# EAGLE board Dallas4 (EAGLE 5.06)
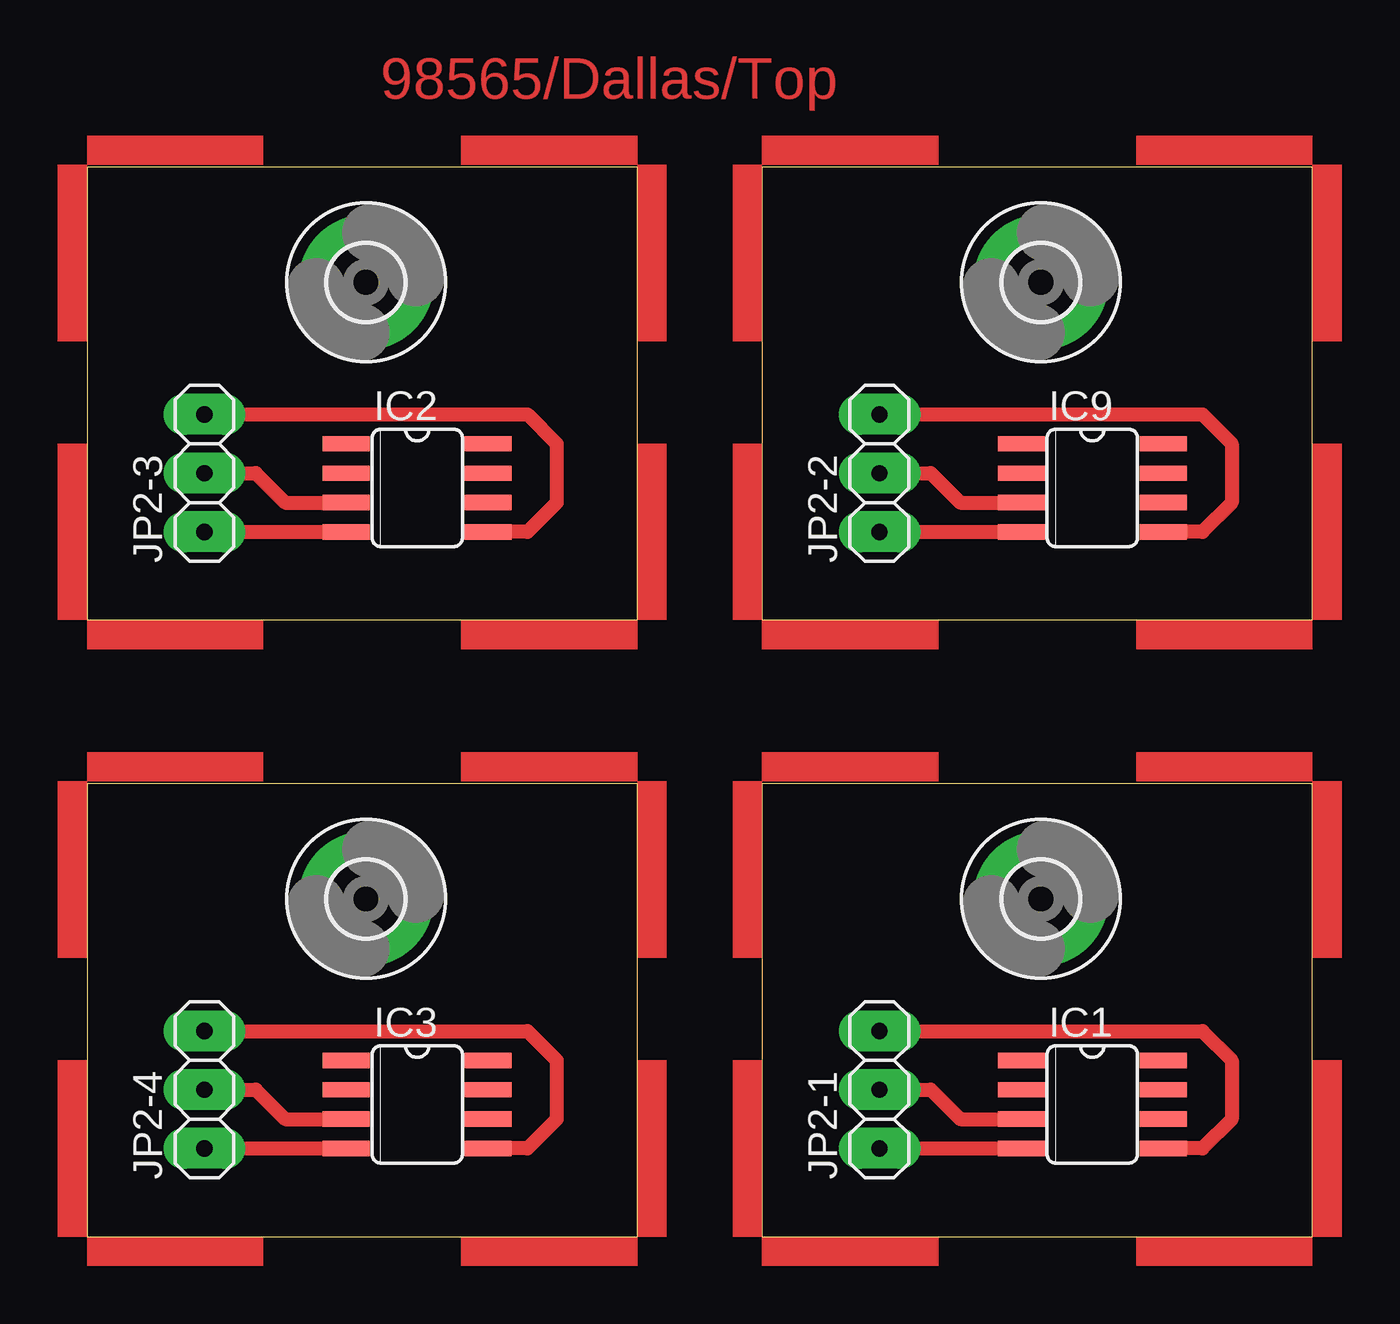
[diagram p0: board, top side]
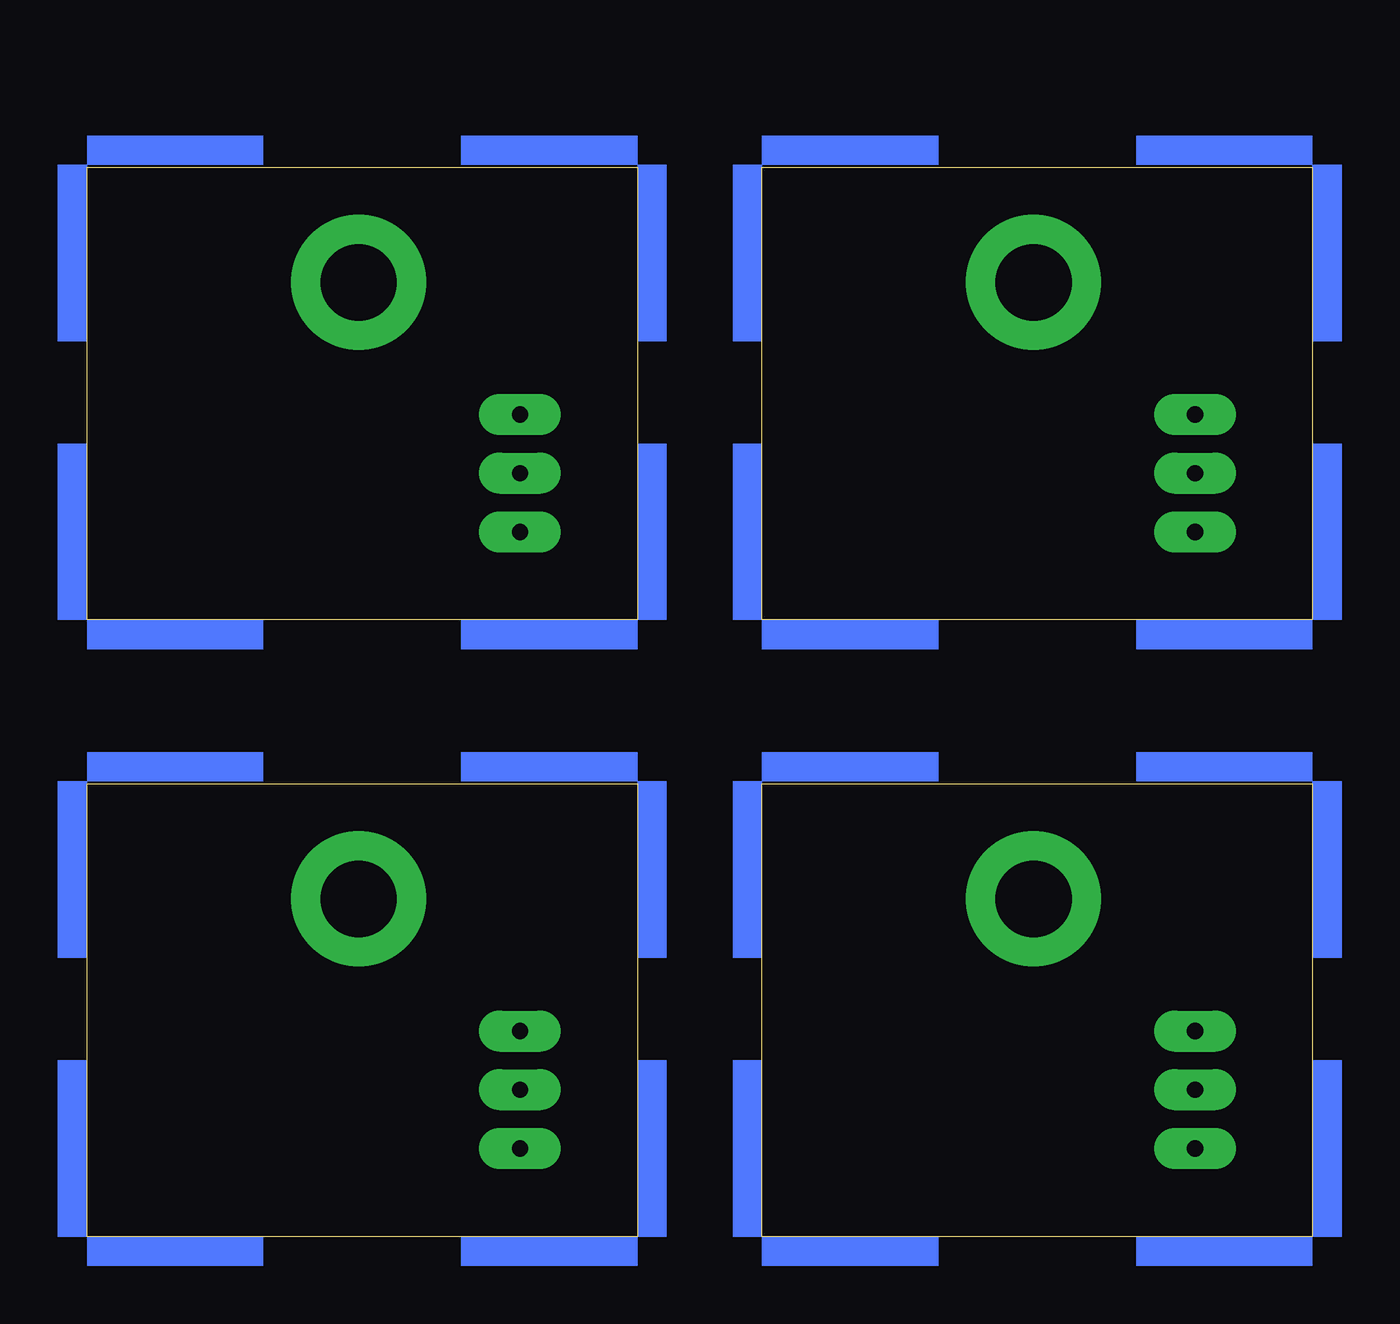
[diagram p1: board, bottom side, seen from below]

Size 53.02 x 46.26 mm. Coordinates in mm from the lower left corner, seen from the top.
Outline: 29.21,26.67 53.02,26.67 53.02,46.26 29.21,46.26 29.21,26.67
Outline: 29.21,0 53.02,0 53.02,19.59 29.21,19.59 29.21,0
Outline: 0,26.67 23.81,26.67 23.81,46.26 0,46.26 0,26.67
Outline: 0,0 23.81,0 23.81,19.59 0,19.59 0,0
Copper layers (1*16): Top 0.035mm / dielectric 1.5mm / Bottom 0.035mm
Design rules "default": minimum track width 10mil, minimum drill 24mil, track to track 8mil, track to pad 8mil, pad to pad 8mil, via to via 8mil, smd to smd 8mil, copper to edge 40mil, drill to drill 8mil, minimum pad ring 10mil, minimum via ring 8mil, stop-mask expansion 4mil, vias tented up to drill 0mil, thermal gap 10mil

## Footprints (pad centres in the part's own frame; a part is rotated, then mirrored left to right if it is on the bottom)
3,3-PAD = drill 3.3 pad 5.842 round: B3,3 0,0
SO08 = smd 0.66 x 2.032: 1 -1.905,-3.073; 2 -0.635,-3.073; 3 0.635,-3.073; 4 1.905,-3.073; 5 1.905,3.073; 6 0.635,3.073; 7 -0.635,3.073; 8 -1.905,3.073
1X03 = drill 0.7 pad 1.778 long: 1 -2.54,0; 2 0,0; 3 2.54,0

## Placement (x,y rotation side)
H1  MOUNT-PAD-ROUND3.3  [3,3-PAD]  41.28,41.27 0 top
H2  MOUNT-PAD-ROUND3.3  [3,3-PAD]  41.28,14.6 0 top
H3  MOUNT-PAD-ROUND3.3  [3,3-PAD]  12.07,41.27 0 top
H4  MOUNT-PAD-ROUND3.3  [3,3-PAD]  12.07,14.6 0 top
IC1  DS18B20Z  [SO08]  43.5,5.71 270 top
IC2  DS18B20Z  [SO08]  14.29,32.38 270 top
IC3  DS18B20Z  [SO08]  14.29,5.71 270 top
IC9  DS18B20Z  [SO08]  43.5,32.38 270 top
JP2-1  DALLAS  [1X03]  34.29,6.35 90 top
JP2-2  DALLAS  [1X03]  34.29,33.02 90 top
JP2-3  DALLAS  [1X03]  5.08,33.02 90 top
JP2-4  DALLAS  [1X03]  5.08,6.35 90 top
U$1  [ANGLE-ARROW-NW1-16]  29.21,46.35 0 top
U$2  [ANGLE-ARROW-NW1-16]  29.21,26.67 90 top
U$3  [ANGLE-ARROW-NW1-16]  53.02,26.67 180 top
U$4  [ANGLE-ARROW-NW1-16]  53.02,46.35 270 top
U$5  [ANGLE-ARROW-NW1-16]  29.21,19.68 0 top
U$6  [ANGLE-ARROW-NW1-16]  29.21,0 90 top
U$7  [ANGLE-ARROW-NW1-16]  53.02,0 180 top
U$8  [ANGLE-ARROW-NW1-16]  53.02,19.68 270 top
U$9  [ANGLE-ARROW-NW1-16]  0,46.35 0 top
U$10  [ANGLE-ARROW-NW1-16]  0,26.67 90 top
U$11  [ANGLE-ARROW-NW1-16]  23.81,26.67 180 top
U$12  [ANGLE-ARROW-NW1-16]  23.81,46.35 270 top
U$13  [ANGLE-ARROW-NW1-16]  0,19.68 0 top
U$14  [ANGLE-ARROW-NW1-16]  0,0 90 top
U$15  [ANGLE-ARROW-NW1-16]  23.81,0 180 top
U$16  [ANGLE-ARROW-NW1-16]  23.81,19.68 270 top

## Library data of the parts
H1-H4 = holes
IC1-IC3 IC9 = 1wire
JP2-1-JP2-4 = pinhead
U$1-U$16 = marks

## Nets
GND: IC9.5 JP2-2.3
GND1: IC1.5 JP2-1.3
GND2: IC2.5 JP2-3.3
GND3: IC3.5 JP2-4.3
N$1: IC9.4 JP2-2.1
N$2: IC9.3 JP2-2.2
N$3: IC1.4 JP2-1.1
N$4: IC1.3 JP2-1.2
N$5: IC2.4 JP2-3.1
N$6: IC2.3 JP2-3.2
N$7: IC3.4 JP2-4.1
N$8: IC3.3 JP2-4.2

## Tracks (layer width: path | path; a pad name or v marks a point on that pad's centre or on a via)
GND
  Top 0.61: IC9.5 48.26,30.48 49.53,31.75 49.53,34.29 48.26,35.56 JP2-2.3
GND1
  Top 0.61: IC1.5 48.26,3.81 49.53,5.08 49.53,7.62 48.26,8.89 JP2-1.3
GND2
  Top 0.61: IC2.5 19.05,30.48 20.32,31.75 20.32,34.29 19.05,35.56 JP2-3.3
GND3
  Top 0.61: IC3.5 19.05,3.81 20.32,5.08 20.32,7.62 19.05,8.89 JP2-4.3
N$1
  Top 0.61: JP2-2.1 IC9.4
N$2
  Top 0.61: JP2-2.2 36.51,33.02 37.78,31.75 IC9.3
N$3
  Top 0.61: JP2-1.1 IC1.4
N$4
  Top 0.61: JP2-1.2 36.51,6.35 37.78,5.08 IC1.3
N$5
  Top 0.61: JP2-3.1 IC2.4
N$6
  Top 0.61: JP2-3.2 7.3,33.02 8.57,31.75 IC2.3
N$7
  Top 0.61: JP2-4.1 IC3.4
N$8
  Top 0.61: JP2-4.2 7.3,6.35 8.57,5.08 IC3.3

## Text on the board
Top: 98565/Dallas/Top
